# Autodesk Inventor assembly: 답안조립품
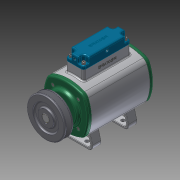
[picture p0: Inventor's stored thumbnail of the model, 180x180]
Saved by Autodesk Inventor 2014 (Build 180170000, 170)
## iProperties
Created: 2016-10
Part Number: 답안조립품
Document SubType Name: Assembly
Designer: user
Mass: 3558.91 g
Surface Area: 2685.97 cm^2
Volume: 916.99 cm^3
Density: 3.88108 g/cm^3
Author: user
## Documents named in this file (18)
- C:\Users\user\Desktop\361008V1004\답안조립품.iam
- C:\Users\user\Desktop\361008V1004\본체.ipt
- C:\Users\user\Desktop\361008V1004\V-벨트풀리.ipt
- C:\Users\user\Desktop\361008V1004\뒷커버.ipt
- C:\Users\user\Desktop\361008V1004\멈춤나사 M4x5.ipt
- C:\Users\user\Desktop\361008V1004\베어링 6203.ipt
- C:\Users\user\Desktop\361008V1004\볼트 M4 x 12.ipt
- C:\Users\user\Desktop\361008V1004\볼트 M4 x 16.ipt
- C:\Users\user\Desktop\361008V1004\부시.ipt
- C:\Users\user\Desktop\361008V1004\스프링1.ipt
- C:\Users\user\Desktop\361008V1004\스프링2.ipt
- C:\Users\user\Desktop\361008V1004\스프링3.ipt
- C:\Users\user\Desktop\361008V1004\슬라이드.ipt
- C:\Users\user\Desktop\361008V1004\앞커버.ipt
- C:\Users\user\Desktop\361008V1004\오일실 17 30 8.ipt
- C:\Users\user\Desktop\361008V1004\축.ipt
- C:\Users\user\Desktop\361008V1004\키 - 5 x 5 x 18.ipt
- C:\Users\user\Desktop\361008V1004\헤더커버.ipt
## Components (4 placed, 3 different names)
1. V-벨트풀리:1 — Insert:7, Angle:2, Mate:1
2. 7-베어링 6203:1 — Insert:1, Insert:3
3. 헤더커버:1 — Insert:15, Insert:16, Insert:17, Insert:18, Insert:19
4. 7-베어링 6203:2 — Insert:2, Insert:4
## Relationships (12: Insert 10, Angle 1, Mate 1)
- Insert:1: 7-베어링 6203:1
- Insert:2: 7-베어링 6203:2
- Insert:3: 7-베어링 6203:1
- Insert:4: 7-베어링 6203:2
- Insert:7: V-벨트풀리:1
- Angle:2: V-벨트풀리:1
- Mate:1: V-벨트풀리:1
- Insert:15: 헤더커버:1
- Insert:16: 헤더커버:1
- Insert:17: 헤더커버:1
- Insert:18: 헤더커버:1
- Insert:19: 헤더커버:1
